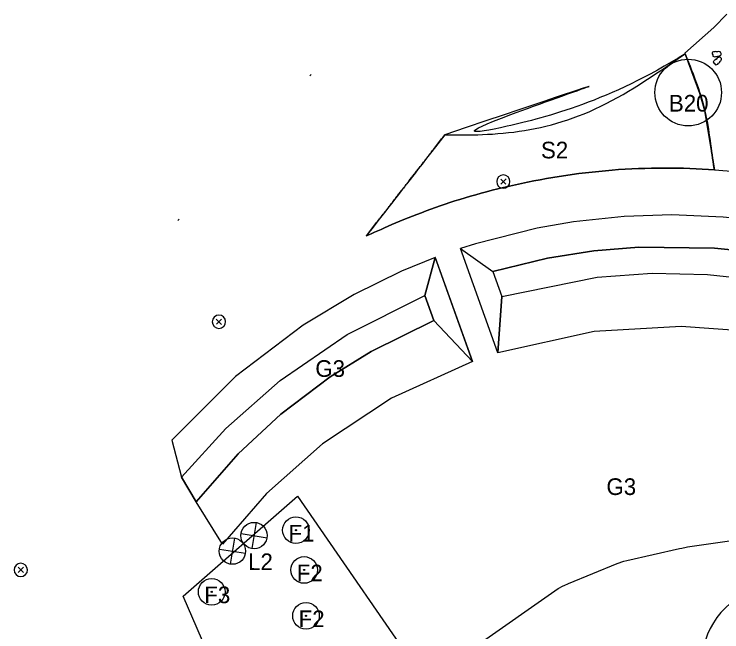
# Model space of a CAD drawing. Extents: x 0 to 512122, y 0 to 6212554.
# Drawn here: x 511378 to 511431.1, y 6211428.9 to 6211475.3 of the extents above; entities that cross this region are included whole.
import ezdxf

# ---------------------------------------------------------------- set-up
doc = ezdxf.new("R2010")
doc.units = 0
for name, color, linetype in [('_lights', 7, 'Continuous'), ('_Låge L2', 7, 'Continuous'), ('_Marksten', 7, 'Continuous'), ('_ny fruit trees', 7, 'Continuous'), ('_Paths', 7, 'Continuous'), ('_S2_skovjorbær', 7, 'Continuous'), ('_Spredmingskorridor', 7, 'Continuous'), ('Clouds', 7, 'Continuous'), ('L40 jord udlagt muld og grøft', 7, 'Continuous'), ('MatrikelnummerMaster', 7, 'Continuous'), ('TV_U_AFM_Symbl_Gul', 7, 'Continuous'), ('TV_U_LYS_iWay', 7, 'Continuous'), ('TV_U_LYS_Mastenummer', 7, 'Continuous'), ('TV_U_LYS_Nyx330-Trafiksti-x2', 7, 'Continuous')]:
    doc.layers.add(name, color=color, linetype=linetype)

msp = doc.modelspace()

# ---------------------------------------------------------------- linework, layer by layer
at = {"layer": '_lights'}
for p, q in [((511414.526, 6211462.901), (511414.92, 6211462.507)), ((511414.924, 6211462.905), (511414.53, 6211462.511)), ((511393.175, 6211452.389), (511393.569, 6211451.994)), ((511393.573, 6211452.393), (511393.179, 6211451.998)), ((511378.299, 6211433.764), (511378.693, 6211433.369)), ((511378.697, 6211433.768), (511378.303, 6211433.373))]:
    msp.add_line(p, q, dxfattribs=at)
for centre, start, end in [((511414.723, 6211462.704), 315.5636, 315), ((511414.723, 6211462.704), 315, 315.5636), ((511393.372, 6211452.192), 315.5636, 315), ((511393.372, 6211452.192), 315, 315.5636), ((511378.496, 6211433.567), 315.5636, 315), ((511378.496, 6211433.567), 315, 315.5636)]:
    msp.add_arc(centre, 0.5, start, end, dxfattribs=at)
at = {"layer": '_Låge L2'}
for p, q in [((511396.166, 6211437.12), (511395.848, 6211435.168)), ((511395.031, 6211436.303), (511396.983, 6211435.985)), ((511394.542, 6211435.953), (511394.224, 6211434.001)), ((511393.407, 6211435.136), (511395.359, 6211434.818))]:
    msp.add_line(p, q, dxfattribs=at)
for centre in [(511396.007, 6211436.144), (511394.383, 6211434.977)]:
    msp.add_circle(centre, 0.989, dxfattribs=at)
at = {"layer": '_Marksten'}
for points in [[(511430.441, 6211472.131), (511430.533, 6211472.093), (511430.591, 6211472.076), (511430.673, 6211472.099), (511430.738, 6211472.097), (511430.803, 6211472.095), (511430.837, 6211472.126), (511430.883, 6211472.13), (511430.945, 6211472.135), (511430.996, 6211472.157), (511431.062, 6211472.202), (511431.074, 6211472.234), (511431.073, 6211472.263), (511431.072, 6211472.307), (511431.055, 6211472.381), (511431.024, 6211472.419), (511430.993, 6211472.434), (511430.943, 6211472.45), (511430.872, 6211472.457), (511430.797, 6211472.442), (511430.72, 6211472.435), (511430.655, 6211472.461), (511430.595, 6211472.442), (511430.547, 6211472.445), (511430.507, 6211472.439), (511430.433, 6211472.412), (511430.413, 6211472.371), (511430.413, 6211472.285), (511430.443, 6211472.23)], [(511430.663, 6211471.471), (511430.759, 6211471.496), (511430.815, 6211471.518), (511430.866, 6211471.586), (511430.919, 6211471.624), (511430.972, 6211471.662), (511430.98, 6211471.708), (511431.014, 6211471.738), (511431.06, 6211471.78), (511431.088, 6211471.829), (511431.112, 6211471.905), (511431.102, 6211471.938), (511431.085, 6211471.96), (511431.057, 6211471.994), (511430.998, 6211472.043), (511430.95, 6211472.054), (511430.917, 6211472.047), (511430.867, 6211472.029), (511430.806, 6211471.991), (511430.756, 6211471.934), (511430.699, 6211471.881), (511430.631, 6211471.863), (511430.596, 6211471.811), (511430.556, 6211471.784), (511430.528, 6211471.755), (511430.486, 6211471.688), (511430.495, 6211471.644), (511430.547, 6211471.576), (511430.604, 6211471.55)]]:
    msp.add_lwpolyline(points, close=True, dxfattribs=at)
at = {"layer": '_ny fruit trees'}
for centre, radius in [((511399.152, 6211436.548), 1), ((511399.152, 6211436.548), 0.0426), ((511399.767, 6211433.561), 1), ((511399.767, 6211433.561), 0.0426), ((511392.826, 6211431.92), 1), ((511392.826, 6211431.92), 0.0426), ((511399.908, 6211430.12), 1), ((511399.908, 6211430.12), 0.0426)]:
    msp.add_circle(centre, radius, dxfattribs=at)
at = {"layer": '_Paths'}
for points in [[(511450.039, 6211448.86), (511448.659, 6211442.81), (511441.758, 6211430.614), (511427.385, 6211422.182), (511415.868, 6211415.798), (511410.87, 6211405.413), (511411.537, 6211394.313), (511413.909, 6211386.762), (511418.057, 6211376.543), (511422.936, 6211366.106), (511450.039, 6211448.86), (511422.936, 6211366.106)], [(511452.493, 6211448.381), (511452.097, 6211446.356), (511450.738, 6211439.396), (511444.066, 6211426.759), (511429.553, 6211420.175), (511417.018, 6211415.504), (511412.404, 6211405.178), (511413.418, 6211395.795), (511416.522, 6211386.629), (511420.496, 6211376.909), (511423.945, 6211369.766), (511425.261, 6211367.041)]]:
    msp.add_open_spline(points, degree=3, dxfattribs=at)
at = {"layer": '_S2_skovjorbær'}
for points, degree in [([(511428.366, 6211472.299), (511422.752, 6211468.771), (511413.036, 6211466.219), (511410.33, 6211466.219), (511428.366, 6211472.299), (511410.33, 6211466.219)], 3), ([(511410.33, 6211466.219), (511411.232, 6211466.201), (511415.48, 6211466.114), (511421.976, 6211467.854), (511426.548, 6211471.034), (511428.366, 6211472.299)], 3), ([(511430.566, 6211463.587), (511430.383, 6211464.578), (511430.075, 6211468.04), (511429.067, 6211470.552), (511428.366, 6211472.299)], 3), ([(511428.366, 6211472.299), (511429.067, 6211470.552), (511430.075, 6211468.04), (511430.383, 6211464.578), (511430.566, 6211463.587)], 3), ([(511410.33, 6211466.219), (511404.433, 6211458.625), (511410.33, 6211466.219), (511404.433, 6211458.625)], 3), ([(511404.433, 6211458.625), (511406.399, 6211461.157), (511408.365, 6211463.688), (511410.33, 6211466.219)], 2), ([(511404.433, 6211458.625), (511405.437, 6211459.078), (511408.712, 6211460.555), (511414.87, 6211462.465), (511422.904, 6211463.795), (511428.171, 6211463.761), (511430.566, 6211463.587)], 3), ([(511430.566, 6211463.587), (511428.171, 6211463.761), (511422.904, 6211463.795), (511414.87, 6211462.465), (511408.712, 6211460.555), (511405.437, 6211459.078), (511404.433, 6211458.625)], 3)]:
    msp.add_open_spline(points, degree=degree, dxfattribs=at)
at = {"layer": '_Spredmingskorridor'}
msp.add_lwpolyline([(511431.505, 6211475.271), (511430.537, 6211474.276), (511428.347, 6211472.355), (511428.366, 6211472.299), (511428.593, 6211471.632), (511429.462, 6211469.348), (511429.835, 6211468.037), (511430.28, 6211465.307), (511430.566, 6211463.587), (511432.775, 6211463.422)], dxfattribs=at)
at = {"layer": 'Clouds'}
msp.add_arc((511435.682, 6211426.381), 6.1, 52.9408, 197.9408, dxfattribs=at)
at = {"layer": 'L40 jord udlagt muld og grøft'}
msp.add_line((511390.56, 6211440.515), (511391.658, 6211438.688), dxfattribs=at)
for points in [[(511448.281, 6211455.2), (511450.091, 6211457.845), (511446.592, 6211458.144), (511441.032, 6211458.856), (511435.871, 6211459.561), (511431.226, 6211460.037), (511427.363, 6211460.201), (511423.803, 6211460.095), (511419.987, 6211459.694), (511417.262, 6211459.221), (511412.63, 6211458.047), (511411.501, 6211457.69), (511413.925, 6211455.968), (511418.034, 6211456.964), (511421.527, 6211457.51), (511424.901, 6211457.788), (511430.573, 6211457.715), (511435.577, 6211457.214), (511438.812, 6211456.779), (511445.318, 6211455.907)], [(511411.501, 6211457.69), (511413.925, 6211455.968), (511414.602, 6211454.082), (511414.315, 6211449.849)], [(511408.834, 6211454.167), (511409.615, 6211457.023), (511407.066, 6211455.978), (511403.512, 6211454.235), (511399.693, 6211451.943), (511394.619, 6211448.08), (511389.831, 6211443.313), (511390.56, 6211440.515), (511393.899, 6211444.19), (511397.977, 6211447.789), (511402.998, 6211451.225)], [(511412.417, 6211449.217), (511409.511, 6211452.282), (511408.834, 6211454.167), (511409.615, 6211457.023)], [(511449.767, 6211448.758), (511444.09, 6211450.012), (511432.94, 6211451.482), (511428.082, 6211451.824), (511421.542, 6211451.463), (511414.315, 6211449.849), (511414.602, 6211454.082), (511421.762, 6211455.523), (511425.895, 6211455.823), (511430.043, 6211455.743), (511437.787, 6211454.903), (511444.951, 6211453.937), (511448.134, 6211453.202)], [(511390.56, 6211440.515), (511393.899, 6211444.19), (511397.977, 6211447.789), (511402.998, 6211451.225), (511408.834, 6211454.167), (511409.511, 6211452.282), (511404.807, 6211449.963), (511401.734, 6211448.053), (511398.026, 6211445.251), (511394.818, 6211442.275), (511391.658, 6211438.688)], [(511409.511, 6211452.283), (511412.417, 6211449.217), (511406.325, 6211446.448), (511401.142, 6211443.027), (511396.942, 6211439.301), (511393.638, 6211435.509), (511391.658, 6211438.688), (511394.818, 6211442.275), (511398.026, 6211445.251), (511401.734, 6211448.053), (511404.807, 6211449.963)]]:
    msp.add_lwpolyline(points, close=True, dxfattribs=at)
for points in [[(511440.382, 6211456.569), (511438.812, 6211456.779), (511435.577, 6211457.214), (511430.573, 6211457.715), (511424.901, 6211457.788), (511421.527, 6211457.51), (511418.034, 6211456.964), (511413.925, 6211455.968), (511414.602, 6211454.082), (511421.762, 6211455.523), (511425.895, 6211455.823), (511430.043, 6211455.743), (511437.787, 6211454.903), (511443.659, 6211454.111)], [(511409.615, 6211457.023), (511408.834, 6211454.167), (511409.511, 6211452.282), (511412.417, 6211449.217), (511409.615, 6211457.024)], [(511409.511, 6211452.283), (511412.417, 6211449.217), (511406.325, 6211446.448), (511401.142, 6211443.027), (511396.942, 6211439.301), (511393.638, 6211435.509), (511391.658, 6211438.688), (511394.818, 6211442.275), (511398.026, 6211445.251), (511401.734, 6211448.053), (511404.807, 6211449.963), (511409.511, 6211452.282)]]:
    msp.add_lwpolyline(points, dxfattribs=at)
at = {"layer": 'MatrikelnummerMaster'}
msp.add_lwpolyline([(511390.691, 6211431.595), (511399.257, 6211439.106), (511409.348, 6211424.486), (511412.596, 6211418.316), (511405.933, 6211404.978), (511401.201, 6211407.342), (511390.691, 6211431.595), (511390.691, 6211431.595), (511390.691, 6211431.595), (511390.691, 6211431.595), (511390.691, 6211431.595)], dxfattribs=at)
at = {"layer": 'TV_U_LYS_iWay'}
for p, q in [((511400.284, 6211470.737), (511400.194, 6211470.639)), ((511390.389, 6211459.894), (511390.287, 6211459.783))]:
    msp.add_line(p, q, dxfattribs=at)
at = {"layer": 'TV_U_LYS_Mastenummer'}
msp.add_circle((511428.602, 6211469.389), 2.5, dxfattribs=at)
msp.add_circle((511428.602, 6211469.389), 2.5, dxfattribs=at)
at = {"layer": 'TV_U_LYS_Nyx330-Trafiksti-x2'}
msp.add_lwpolyline([(511412.652, 6211427.857), (511418.83, 6211432.183), (511419.216, 6211432.368), (511419.288, 6211432.402), (511419.617, 6211432.556), (511423.28, 6211434.057), (511423.76, 6211434.224), (511423.992, 6211434.285), (511427.95, 6211435.172), (511428.119, 6211435.204), (511428.449, 6211435.283), (511428.555, 6211435.3), (511432.576, 6211435.879)], dxfattribs=at)

# ---------------------------------------------------------------- texts
at = {"layer": 'TV_U_AFM_Symbl_Gul'}
for s, p in [('B20', (511427.152, 6211467.961)), ('S2', (511417.549, 6211464.448)), ('G3', (511400.607, 6211448.053)), ('G3', (511422.464, 6211439.189)), ('F1', (511398.598, 6211435.699)), ('F2', (511399.212, 6211432.713)), ('F3', (511392.272, 6211431.072)), ('F2', (511399.353, 6211429.272))]:
    msp.add_text(s, height=1.25, dxfattribs=at).set_placement(p)
msp.add_text('L2', height=1.25, rotation=359.545, dxfattribs=at).set_placement((511395.555, 6211433.563))

doc.saveas('drawing.dxf')
